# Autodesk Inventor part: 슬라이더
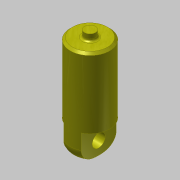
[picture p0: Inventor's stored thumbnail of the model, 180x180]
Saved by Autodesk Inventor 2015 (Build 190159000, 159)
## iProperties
Created: 2016-08
Part Number: 슬라이더
Material: 강철, 탄소
Document SubType Name: Modeling
Designer: mduedu
Density: 7.87 g/cm^3
Appearance: 노란색
Mass: 75.7902 g
Surface Area: 29.7311 cm^2
Volume: 9.63026 cm^3
Author: mduedu
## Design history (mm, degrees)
sketch "스케치1"
  geometry: C1 r 9 at (0, 0); 1 further point
  constraints: 1 centre point, 1 coincident
  dimensions: "d0" = 18 diameter of C1
extrude "돌출1" new body sketch "스케치1" distance "d1" = 45; taper "d2" = 0 deg
fillet "모깎기1" dims "d21" = 6
sketch "스케치6"
  geometry: L1 (9, 6)-(9, 45) reference; L2 (-9, 6)-(-9, 45) reference; L3 (9, 45)-(-9, 45) reference; L4 (0, 45)-(0, 0); L5 (9, 13)-(4, 13); L6 (4, 13)-(4, 0); L7 (4, 0)-(9, 0); L8 (9, 0)-(9, 13); L9 (-9, 13)-(-4, 13); L10 (-4, 13)-(-4, 0); L11 (-4, 0)-(-9, 0); L12 (-9, 0)-(-9, 13)
  constraints: 18 end point, 4 symmetric about line, 2 parallel, 2 perpendicular, 1 horizontal, 1 horizontal alignment, 1 midpoint, 1 point on line
  dimensions: "d22" = 13 distance of L7.end L5.start; "d24" = 4 distance between parallel lines of L6 L4
extrude "돌출5" cut sketch "스케치6" stored distance "d25" = 8; taper "d26" = 0 deg
sketch "스케치8"
  geometry: C1 r 3 at (6, 0); 1 further point
  constraints: 1 centre point, 1 horizontal alignment
  dimensions: "d27" = 6 diameter of C1; "d28" = 6 distance of point (0, 0) C1.centre
extrude "돌출6" cut sketch "스케치8" stored distance "d29" = 8; taper "d30" = 0 deg
chamfer "모따기2" distance "d43" = 1; stored, may be unused: second distance "d44" = 2, angle "d45" = 30 deg
sketch "스케치9"
  geometry: C1 r 2.5 at (0, 0); 1 further point
  constraints: 1 centre point, 1 coincident
  dimensions: "d47" = 5 diameter of C1
extrude "돌출7" join sketch "스케치9" distance "d48" = 3; taper "d49" = 0 deg
fillet "모깎기2" dims "d50" = 1
node "솔리드1"
